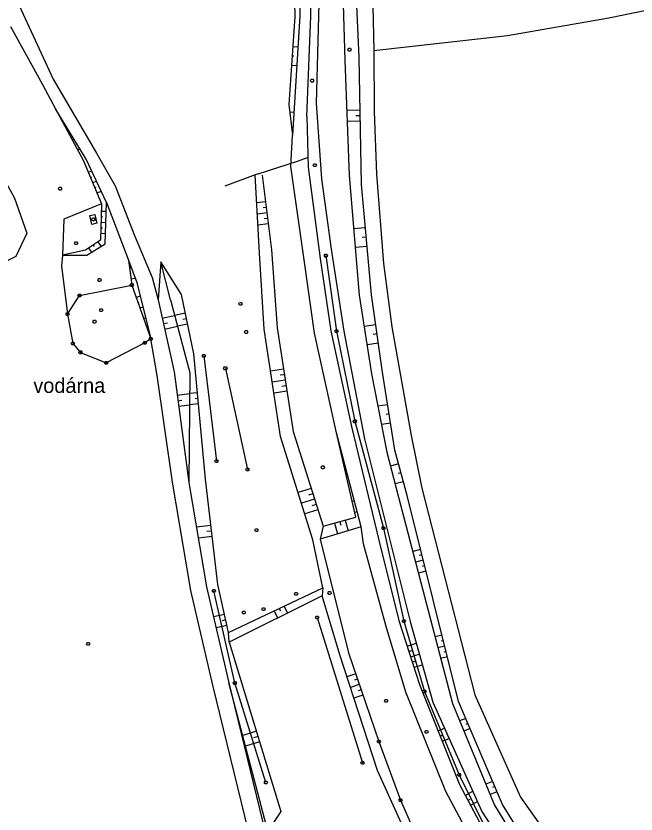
# Model space of a CAD drawing. Extents: x -664960 to -662754, y -993849 to -991145.
# Drawn here: x -663555.7 to -663422.3, y -993033.1 to -992861.4 of the extents above; entities that cross this region are included whole.
import ezdxf

# ---------------------------------------------------------------- set-up
doc = ezdxf.new("R2010")
doc.units = 0
for name, color, linetype in [('Vrstva 13', 7, 'Continuous'), ('Vrstva 24', 7, 'Continuous'), ('Vrstva 27', 7, 'Continuous'), ('Vrstva 29', 7, 'Continuous'), ('Vrstva 33', 7, 'Continuous'), ('Vrstva 63', 7, 'Continuous')]:
    doc.layers.add(name, color=color, linetype=linetype)

msp = doc.modelspace()

# ---------------------------------------------------------------- linework, layer by layer
at = {"layer": 'Vrstva 13'}
for points in [[(-663542.493, -992909.961), (-663542.313, -992910.261), (-663542.493, -992910.561), (-663542.853, -992910.561), (-663543.033, -992910.261), (-663542.853, -992909.961), (-663542.493, -992909.961)], [(-663537.472, -992917.871), (-663537.292, -992918.171), (-663537.472, -992918.471), (-663537.832, -992918.471), (-663538.012, -992918.171), (-663537.832, -992917.871), (-663537.472, -992917.871)], [(-663489.494, -992958.202), (-663489.314, -992958.502), (-663489.494, -992958.802), (-663489.854, -992958.802), (-663490.034, -992958.502), (-663489.854, -992958.202), (-663489.494, -992958.202)], [(-663503.758, -992971.707), (-663503.578, -992972.007), (-663503.758, -992972.307), (-663504.118, -992972.307), (-663504.298, -992972.007), (-663504.118, -992971.707), (-663503.758, -992971.707)], [(-663539.928, -992996.16), (-663539.748, -992996.46), (-663539.928, -992996.76), (-663540.288, -992996.76), (-663540.468, -992996.46), (-663540.288, -992996.16), (-663539.928, -992996.16)], [(-663475.846, -993008.426), (-663475.666, -993008.726), (-663475.846, -993009.026), (-663476.206, -993009.026), (-663476.386, -993008.726), (-663476.206, -993008.426), (-663475.846, -993008.426)], [(-663467.154, -993015.117), (-663466.974, -993015.417), (-663467.154, -993015.717), (-663467.514, -993015.717), (-663467.694, -993015.417), (-663467.514, -993015.117), (-663467.154, -993015.117)]]:
    msp.add_lwpolyline(points, dxfattribs=at)
at = {"layer": 'Vrstva 24'}
msp.add_lwpolyline([(-663503.56, -992895.37), (-663495.1, -992892.65), (-663492.76, -992891.78)], dxfattribs=at)
at = {"layer": 'Vrstva 27'}
for p, q in [((-663493.095, -992883.033), (-663492.82, -992893.94)), ((-663496.5, -992893.77), (-663496.188, -992887.015)), ((-663492.82, -992893.94), (-663490.26, -992913.59)), ((-663536.17, -992901.51), (-663531.47, -992913.88))]:
    msp.add_line(p, q, dxfattribs=at)
for points in [[(-663493.3, -992747.16), (-663493.74, -992757.17), (-663493.888, -992762.726), (-663494.182, -992775.159), (-663494.693, -992783.58), (-663494.915, -992797.656), (-663495.32, -992822.604), (-663494.616, -992861.372), (-663496.188, -992887.015)], [(-663488.658, -992771.319), (-663486.041, -992777.124), (-663484.479, -992778.312), (-663480.688, -992780.627), (-663479.797, -992784.051), (-663480.225, -992798.776), (-663480.106, -992812.528), (-663479.191, -992846.153), (-663478.672, -992868.89), (-663478.583, -992881.904), (-663478.082, -992895.396), (-663476.627, -992914.637), (-663474.815, -992928.231), (-663470.676, -992951.637), (-663468.34, -992962.956), (-663456.927, -993007.431), (-663447.138, -993029.424), (-663438.677, -993041.464), (-663430.737, -993050.315), (-663424.65, -993058.054), (-663424.821, -993065.561), (-663424.273, -993071.083), (-663422.364, -993076.277)], [(-663493.095, -992883.033), (-663492.196, -992861.424), (-663492.956, -992822.595), (-663492.609, -992797.023), (-663492.331, -992783.259), (-663491.101, -992775.678), (-663489.833, -992782.642), (-663491.019, -992797.262), (-663489.769, -992835.934), (-663490.477, -992858.663), (-663491.12, -992880.1), (-663489.906, -992896.409), (-663487.878, -992911.561), (-663485.118, -992929.166), (-663480.702, -992952.347), (-663470.868, -992991.635), (-663466.023, -993009.002), (-663455.437, -993032.516), (-663446.928, -993045.767), (-663436.64, -993058.03)], [(-663442.777, -993044.277), (-663451.02, -993031.047), (-663460.443, -993008.901), (-663471.546, -992964.515), (-663474.13, -992954.774), (-663476.786, -992938.014), (-663479.196, -992921.39), (-663481.361, -992897.65), (-663481.87, -992870.307), (-663482.894, -992846.181), (-663483.445, -992812.781), (-663483.355, -992807.645), (-663486.558, -992815.716), (-663484.937, -992870.853), (-663484.019, -992895.682), (-663481.827, -992921.432), (-663479.164, -992938.361), (-663475.866, -992955.23), (-663473.364, -992964.906), (-663461.79, -993009.293), (-663452.727, -993031.168), (-663444.935, -993044.005)], [(-663555.42, -992858.21), (-663547.62, -992874.94), (-663538.34, -992890.87), (-663534.33, -992897.95), (-663530.16, -992908.58), (-663526.35, -992917.64), (-663525.07, -992922.44)], [(-663556.8, -992863.63), (-663549.94, -992876.15), (-663547.12, -992881.32)], [(-663292.32, -993232.82), (-663314.09, -993212.62), (-663328.7, -993196.3), (-663343.76, -993179.73), (-663358.38, -993164.43), (-663372, -993149.25), (-663389.69, -993127.17), (-663396.18, -993117.78), (-663410.43, -993097.33), (-663424.37, -993080.01), (-663430.1, -993071.8), (-663439.74, -993061.19), (-663449.23, -993051.04), (-663457.96, -993038.08), (-663463.23, -993028.27), (-663471.77, -993006.86), (-663476.02, -992992.74), (-663480.89, -992974.93), (-663481.39, -992971.3), (-663486.69, -992951.1), (-663491.43, -992929.63), (-663493.61, -992914.38), (-663496.5, -992893.77)], [(-663531.47, -992913.88), (-663529.62, -992918.73), (-663526.62, -992930.83)], [(-663490.26, -992913.59), (-663487.91, -992929.15), (-663483.47, -992949.71), (-663477.64, -992974.17), (-663473.27, -992991.48), (-663468.86, -993005.23), (-663460.26, -993026.75), (-663454.82, -993037.02), (-663446.62, -993048.94), (-663437.38, -993059.1)], [(-663525.07, -992922.44), (-663521.64, -992937.94), (-663518.46, -992961.72), (-663514.64, -992984.19), (-663509.85, -993004.83), (-663501.96, -993037.29), (-663497.29, -993056.07), (-663495.2, -993076.09), (-663494.44, -993088.61), (-663492.24, -993113.44), (-663491.4, -993120.78), (-663490.02, -993129.31), (-663486.29, -993143.39), (-663482, -993155.26), (-663474.22, -993166.96), (-663462.98, -993181.7), (-663450.36, -993195.84), (-663435.28, -993211.34), (-663418, -993227.21), (-663404.31, -993240.04), (-663391.6, -993253.92), (-663379.85, -993267.71)], [(-663381.88, -993269.82), (-663387.32, -993265.33), (-663393.79, -993257), (-663407.95, -993241.48), (-663421.02, -993229.28), (-663438.16, -993213.52), (-663452.44, -993198.54), (-663465.76, -993183.63), (-663477.14, -993169.29), (-663485.35, -993156.12), (-663489.97, -993144.37), (-663493.8, -993129.17), (-663494.9, -993123.17), (-663495.36, -993113.85), (-663496.9, -993088.93), (-663497.54, -993077.21), (-663500.56, -993056.55), (-663504.87, -993038.7), (-663505.62, -993036.77), (-663513.31, -993005.37), (-663518.03, -992984.98), (-663521.99, -992961.69), (-663525.31, -992938.73), (-663526.62, -992930.83)]]:
    msp.add_lwpolyline(points, dxfattribs=at)
at = {"layer": 'Vrstva 29'}
for points in [[(-663539.74, -992904.28), (-663538.7, -992904.06), (-663538.26, -992905.96), (-663539.31, -992906.21), (-663539.74, -992904.28)], [(-663538.821, -992904.819), (-663538.641, -992905.119), (-663538.821, -992905.419), (-663539.181, -992905.419), (-663539.361, -992905.119), (-663539.181, -992904.819), (-663538.821, -992904.819)]]:
    msp.add_lwpolyline(points, dxfattribs=at)
at = {"layer": 'Vrstva 33'}
for points in [[(-663537.14, -992924.39), (-663536.96, -992924.69), (-663537.14, -992924.99), (-663537.5, -992924.99), (-663537.68, -992924.69), (-663537.5, -992924.39), (-663537.14, -992924.39)], [(-663538.55, -992926.86), (-663538.37, -992927.16), (-663538.55, -992927.46), (-663538.91, -992927.46), (-663539.09, -992927.16), (-663538.91, -992926.86), (-663538.55, -992926.86)]]:
    msp.add_lwpolyline(points, dxfattribs=at)
at = {"layer": 'Vrstva 63'}
for p, q in [((-663496.111, -992867.961), (-663495.025, -992868.038)), ((-663496.253, -992869.956), (-663495.885, -992869.982)), ((-663496.394, -992871.951), (-663495.269, -992872.031)), ((-663481.659, -992881.629), (-663484.537, -992881.682)), ((-663496.785, -992882.1), (-663495.88, -992881.99)), ((-663481.637, -992882.828), (-663482.588, -992882.846)), ((-663545.786, -992883.802), (-663545.663, -992883.735)), ((-663545.218, -992884.859), (-663545.159, -992884.827)), ((-663496.544, -992884.085), (-663496.364, -992884.063)), ((-663481.615, -992884.028), (-663484.448, -992884.081)), ((-663544.65, -992885.916), (-663544.421, -992885.793)), ((-663496.303, -992886.071), (-663496.129, -992886.049)), ((-663544.082, -992886.973), (-663543.988, -992886.922)), ((-663543.514, -992888.03), (-663543.18, -992887.85)), ((-663542.945, -992889.087), (-663542.817, -992889.017)), ((-663542.377, -992890.144), (-663541.939, -992889.908)), ((-663540.059, -992895.006), (-663539.369, -992894.717)), ((-663539.596, -992896.113), (-663539.35, -992896.01)), ((-663539.133, -992897.22), (-663538.346, -992896.891)), ((-663538.669, -992898.327), (-663538.391, -992898.211)), ((-663538.206, -992899.434), (-663537.322, -992899.064)), ((-663501.994, -992901.372), (-663503.858, -992901.608)), ((-663537.274, -992903.345), (-663536.227, -992903.382)), ((-663501.692, -992903.753), (-663503.734, -992904.012)), ((-663501.843, -992902.562), (-663502.494, -992902.645)), ((-663537.315, -992904.545), (-663536.965, -992904.557)), ((-663501.541, -992904.943), (-663502.251, -992905.033)), ((-663537.399, -992906.943), (-663537.045, -992906.955)), ((-663537.357, -992905.744), (-663536.3, -992905.78)), ((-663501.39, -992906.133), (-663503.61, -992906.416)), ((-663480.512, -992906.958), (-663483.039, -992907.189)), ((-663537.44, -992908.142), (-663536.373, -992908.179)), ((-663480.33, -992908.95), (-663481.176, -992909.027)), ((-663539.032, -992910.635), (-663538.817, -992910.949)), ((-663538.041, -992909.957), (-663537.361, -992910.951)), ((-663540.022, -992911.313), (-663539.414, -992912.201)), ((-663480.149, -992910.942), (-663482.7, -992911.174)), ((-663522.42, -992922.47), (-663524.52, -992914.27)), ((-663531.243, -992915.559), (-663530.85, -992915.506)), ((-663531.082, -992916.748), (-663530.858, -992916.718)), ((-663530.921, -992917.937), (-663529.971, -992917.809)), ((-663529.796, -992921.918), (-663528.908, -992921.601)), ((-663529.394, -992923.048), (-663529.135, -992922.956)), ((-663528.991, -992924.178), (-663528.328, -992923.942)), ((-663528.588, -992925.309), (-663528.405, -992925.243)), ((-663528.185, -992926.439), (-663527.747, -992926.283)), ((-663524.195, -992926.392), (-663521.54, -992925.805)), ((-663519.218, -992925.328), (-663521.54, -992925.805)), ((-663523.936, -992927.564), (-663523.036, -992927.365)), ((-663518.735, -992927.679), (-663520.926, -992928.129)), ((-663518.976, -992926.504), (-663519.728, -992926.658)), ((-663478.266, -992927.807), (-663480.767, -992928.17)), ((-663523.677, -992928.736), (-663520.926, -992928.127)), ((-663477.979, -992929.786), (-663478.804, -992929.906)), ((-663477.692, -992931.766), (-663480.146, -992932.121)), ((-663515.24, -992934.51), (-663512.53, -992957.14)), ((-663510.62, -992937.2), (-663505.88, -992958.97)), ((-663498.101, -992937.366), (-663500.878, -992937.792)), ((-663497.737, -992939.738), (-663500.514, -992940.164)), ((-663497.919, -992938.552), (-663498.844, -992938.694)), ((-663497.555, -992940.924), (-663498.48, -992941.066)), ((-663520.966, -992942.98), (-663518.314, -992942.625)), ((-663516.638, -992942.469), (-663518.314, -992942.625)), ((-663497.374, -992942.11), (-663500.15, -992942.536)), ((-663520.807, -992944.169), (-663519.98, -992944.059)), ((-663520.648, -992945.359), (-663518.333, -992945.049)), ((-663516.416, -992944.859), (-663518.333, -992945.038)), ((-663516.527, -992943.664), (-663517.125, -992943.72)), ((-663475.676, -992945.017), (-663477.797, -992945.353)), ((-663475.363, -992946.992), (-663476.046, -992947.101)), ((-663475.05, -992948.968), (-663477.029, -992949.281)), ((-663482.58, -992969.24), (-663486.69, -992951.1)), ((-663473.344, -992957.738), (-663475.097, -992958.203)), ((-663472.831, -992959.671), (-663473.419, -992959.827)), ((-663472.318, -992961.604), (-663474.096, -992962.075)), ((-663492.161, -992963.023), (-663494.952, -992963.91)), ((-663491.435, -992965.311), (-663494.236, -992966.201)), ((-663491.798, -992964.167), (-663492.729, -992964.463)), ((-663483.36, -992965.799), (-663482.863, -992965.686)), ((-663491.071, -992966.455), (-663492.006, -992966.751)), ((-663483.095, -992966.969), (-663482.916, -992966.929)), ((-663490.708, -992967.598), (-663493.52, -992968.491)), ((-663482.829, -992968.139), (-663482.254, -992968.009)), ((-663489.58, -992971.15), (-663482.58, -992969.24)), ((-663487.142, -992970.485), (-663486.507, -992972.815)), ((-663485.985, -992970.169), (-663485.775, -992970.937)), ((-663484.827, -992969.853), (-663484.205, -992972.133)), ((-663513.716, -992970.999), (-663516.82, -992971.369)), ((-663513.573, -992972.19), (-663514.587, -992972.311)), ((-663481.39, -992971.3), (-663490.24, -992973.92)), ((-663513.431, -992973.382), (-663516.417, -992973.738)), ((-663468.631, -992976.169), (-663470.317, -992976.591)), ((-663468.34, -992977.333), (-663468.897, -992977.473)), ((-663468.048, -992978.498), (-663469.711, -992978.914)), ((-663467.466, -992980.826), (-663469.106, -992981.236)), ((-663467.757, -992979.662), (-663468.307, -992979.799)), ((-663500.108, -992989.368), (-663499.384, -992990.903)), ((-663499.023, -992988.856), (-663498.786, -992989.36)), ((-663497.938, -992988.345), (-663497.236, -992989.832)), ((-663510.79, -992990.158), (-663513.136, -992990.67)), ((-663510.534, -992991.331), (-663511.31, -992991.5)), ((-663490.85, -992990.79), (-663481.13, -993022.05)), ((-663510.278, -992992.503), (-663512.594, -992993.008)), ((-663464.016, -992994.616), (-663465.519, -992994.992)), ((-663471.51, -992996.968), (-663469.555, -992996.341)), ((-663463.725, -992995.78), (-663464.222, -992995.905)), ((-663471.143, -992998.111), (-663470.507, -992997.907)), ((-663463.434, -992996.945), (-663464.913, -992997.315)), ((-663463.143, -992998.109), (-663463.631, -992998.231)), ((-663470.777, -992999.253), (-663468.91, -992998.655)), ((-663462.851, -992999.273), (-663464.308, -992999.637)), ((-663470.41, -993000.396), (-663469.803, -993000.201)), ((-663470.044, -993001.539), (-663468.265, -993000.968)), ((-663482.581, -993002.93), (-663484.484, -993003.576)), ((-663481.81, -993005.203), (-663483.736, -993005.856)), ((-663482.195, -993004.067), (-663482.833, -993004.283)), ((-663481.424, -993006.339), (-663482.07, -993006.558)), ((-663481.039, -993007.476), (-663482.989, -993008.137)), ((-663458.914, -993012.494), (-663460.232, -993013.055)), ((-663458.444, -993013.598), (-663458.887, -993013.786)), ((-663503.941, -993015.26), (-663506.877, -993016.155)), ((-663464.878, -993015.194), (-663463.486, -993014.638)), ((-663457.975, -993014.702), (-663459.313, -993015.272)), ((-663503.591, -993016.407), (-663504.584, -993016.71)), ((-663464.433, -993016.309), (-663463.953, -993016.117)), ((-663463.987, -993017.423), (-663462.5, -993016.828)), ((-663503.241, -993017.555), (-663506.267, -993018.478)), ((-663453.136, -993026.074), (-663454.582, -993026.69)), ((-663452.666, -993027.178), (-663453.151, -993027.385)), ((-663459.03, -993029.073), (-663457.38, -993028.199)), ((-663452.196, -993028.283), (-663453.664, -993028.907)), ((-663458.468, -993030.133), (-663457.941, -993029.854)), ((-663457.906, -993031.194), (-663456.393, -993030.392))]:
    msp.add_line(p, q, dxfattribs=at)
for points in [[(-663493.888, -992762.726), (-663496.142, -992777.214), (-663496.083, -992797.466), (-663496.579, -992822.93), (-663495.652, -992861.485), (-663496.993, -992880.388), (-663496.188, -992887.015)], [(-663363.985, -992907.073), (-663374.41, -992891.386), (-663393.094, -992854.627), (-663428.131, -992861.855), (-663449.923, -992865.664), (-663478.672, -992868.89)], [(-663483.722, -992868.335), (-663483.542, -992868.635), (-663483.722, -992868.935), (-663484.082, -992868.935), (-663484.262, -992868.635), (-663484.082, -992868.335), (-663483.722, -992868.335)], [(-663491.785, -992874.984), (-663491.605, -992875.284), (-663491.785, -992875.584), (-663492.145, -992875.584), (-663492.325, -992875.284), (-663492.145, -992874.984), (-663491.785, -992874.984)], [(-663547.12, -992881.32), (-663541.1, -992892.52), (-663537.22, -992901.79), (-663537.49, -992909.58), (-663540.66, -992911.75), (-663545.65, -992912.85), (-663540.43, -992912.82), (-663536.44, -992910.39), (-663536.17, -992901.51)], [(-663536.17, -992901.51), (-663540.55, -992892.21), (-663547.12, -992881.32)], [(-663491.2, -992893.17), (-663491.02, -992893.47), (-663491.2, -992893.77), (-663491.56, -992893.77), (-663491.74, -992893.47), (-663491.56, -992893.17), (-663491.2, -992893.17)], [(-663503.56, -992895.37), (-663504.17, -992895.57), (-663510.76, -992897.96)], [(-663558.76, -992895.41), (-663555.95, -992900.61), (-663553.28, -992908.14), (-663555.71, -992913.11), (-663558.56, -992914.53), (-663569.41, -992917.2), (-663577.02, -992922.39), (-663583.53, -992932.72)], [(-663489.68, -992984.45), (-663491.78, -992974.06), (-663498.72, -992951.85), (-663502.26, -992928.79), (-663503.3, -992912.43), (-663504.17, -992895.57)], [(-663502.72, -992895.66), (-663500.68, -992911.72), (-663499.46, -992928.5), (-663496.04, -992950.81), (-663489.58, -992971.15), (-663490.24, -992973.92), (-663484.12, -992998.39), (-663477.64, -993017.5), (-663472.94, -993030.11), (-663465.51, -993047.01), (-663461.14, -993055.51), (-663454.98, -993064.07), (-663443.01, -993059.86), (-663449.23, -993051.04)], [(-663545.97, -992898.24), (-663545.79, -992898.54), (-663545.97, -992898.84), (-663546.33, -992898.84), (-663546.51, -992898.54), (-663546.33, -992898.24), (-663545.97, -992898.24)], [(-663537.22, -992901.79), (-663545.32, -992905.12), (-663545.65, -992912.85), (-663545.87, -992915.13), (-663544.55, -992925.53), (-663543.42, -992931.83), (-663541.78, -992933.75), (-663536.28, -992936.02)], [(-663531.47, -992913.88), (-663530.74, -992919.27), (-663526.62, -992930.83)], [(-663509.95, -992994.01), (-663512.2, -992983.69), (-663514.91, -992961), (-663517.42, -992934.09), (-663520.04, -992921.32), (-663524.52, -992914.27), (-663525.07, -992922.44)], [(-663488.8, -992912.64), (-663488.62, -992912.94), (-663488.8, -992913.24), (-663489.16, -992913.24), (-663489.34, -992912.94), (-663489.16, -992912.64), (-663488.8, -992912.64)], [(-663488.98, -992912.94), (-663486.69, -992929.18), (-663482.79, -992948.58), (-663476.6, -992971.57), (-663472.24, -992991.59), (-663467.82, -993006.73), (-663460.34, -993024.66), (-663454.22, -993037), (-663446.26, -993048.23), (-663437.77, -993057.47)], [(-663544.55, -992925.53), (-663542.02, -992921.54), (-663530.74, -992919.27)], [(-663530.56, -992918.97), (-663530.38, -992919.27), (-663530.56, -992919.57), (-663530.92, -992919.57), (-663531.1, -992919.27), (-663530.92, -992918.97), (-663530.56, -992918.97)], [(-663541.84, -992921.24), (-663541.66, -992921.54), (-663541.84, -992921.84), (-663542.2, -992921.84), (-663542.38, -992921.54), (-663542.2, -992921.24), (-663541.84, -992921.24)], [(-663522.42, -992922.47), (-663518.28, -992938.15), (-663518.46, -992961.72)], [(-663507.2, -992923.01), (-663507.02, -992923.31), (-663507.2, -992923.61), (-663507.56, -992923.61), (-663507.74, -992923.31), (-663507.56, -992923.01), (-663507.2, -992923.01)], [(-663544.37, -992925.23), (-663544.19, -992925.53), (-663544.37, -992925.83), (-663544.73, -992925.83), (-663544.91, -992925.53), (-663544.73, -992925.23), (-663544.37, -992925.23)], [(-663505.97, -992929.08), (-663505.79, -992929.38), (-663505.97, -992929.68), (-663506.33, -992929.68), (-663506.51, -992929.38), (-663506.33, -992929.08), (-663505.97, -992929.08)], [(-663486.51, -992928.88), (-663486.33, -992929.18), (-663486.51, -992929.48), (-663486.87, -992929.48), (-663487.05, -992929.18), (-663486.87, -992928.88), (-663486.51, -992928.88)], [(-663526.62, -992930.83), (-663527.91, -992931.7), (-663536.28, -992936.02)], [(-663527.73, -992931.4), (-663527.55, -992931.7), (-663527.73, -992932), (-663528.09, -992932), (-663528.27, -992931.7), (-663528.09, -992931.4), (-663527.73, -992931.4)], [(-663526.44, -992930.53), (-663526.26, -992930.83), (-663526.44, -992931.13), (-663526.8, -992931.13), (-663526.98, -992930.83), (-663526.8, -992930.53), (-663526.44, -992930.53)], [(-663543.24, -992931.53), (-663543.06, -992931.83), (-663543.24, -992932.13), (-663543.6, -992932.13), (-663543.78, -992931.83), (-663543.6, -992931.53), (-663543.24, -992931.53)], [(-663541.6, -992933.45), (-663541.42, -992933.75), (-663541.6, -992934.05), (-663541.96, -992934.05), (-663542.14, -992933.75), (-663541.96, -992933.45), (-663541.6, -992933.45)], [(-663515.06, -992934.21), (-663514.88, -992934.51), (-663515.06, -992934.81), (-663515.42, -992934.81), (-663515.6, -992934.51), (-663515.42, -992934.21), (-663515.06, -992934.21)], [(-663536.1, -992935.72), (-663535.92, -992936.02), (-663536.1, -992936.32), (-663536.46, -992936.32), (-663536.64, -992936.02), (-663536.46, -992935.72), (-663536.1, -992935.72)], [(-663510.44, -992936.9), (-663510.26, -992937.2), (-663510.44, -992937.5), (-663510.8, -992937.5), (-663510.98, -992937.2), (-663510.8, -992936.9), (-663510.44, -992936.9)], [(-663482.61, -992948.28), (-663482.43, -992948.58), (-663482.61, -992948.88), (-663482.97, -992948.88), (-663483.15, -992948.58), (-663482.97, -992948.28), (-663482.61, -992948.28)], [(-663512.35, -992956.84), (-663512.17, -992957.14), (-663512.35, -992957.44), (-663512.71, -992957.44), (-663512.89, -992957.14), (-663512.71, -992956.84), (-663512.35, -992956.84)], [(-663505.7, -992958.67), (-663505.52, -992958.97), (-663505.7, -992959.27), (-663506.06, -992959.27), (-663506.24, -992958.97), (-663506.06, -992958.67), (-663505.7, -992958.67)], [(-663476.42, -992971.27), (-663476.24, -992971.57), (-663476.42, -992971.87), (-663476.78, -992971.87), (-663476.96, -992971.57), (-663476.78, -992971.27), (-663476.42, -992971.27)], [(-663509.79, -992996.09), (-663509.95, -992994.01), (-663489.68, -992984.45), (-663489.83, -992986.14)], [(-663512.94, -992984.74), (-663512.76, -992985.04), (-663512.94, -992985.34), (-663513.3, -992985.34), (-663513.48, -992985.04), (-663513.3, -992984.74), (-663512.94, -992984.74)], [(-663501.9, -993026.28), (-663508.6, -993004.89), (-663513.12, -992985.04)], [(-663439.74, -993061.19), (-663447.96, -993066.95), (-663455.1, -993068.27), (-663462.83, -993055.39), (-663468.65, -993044.14), (-663477.89, -993023.69), (-663486.03, -992998.86), (-663489.83, -992986.14), (-663509.79, -992996.09), (-663498.66, -993032.57), (-663501.47, -993036.75), (-663509.85, -993004.83)], [(-663495.2, -992985.4), (-663495.02, -992985.7), (-663495.2, -992986), (-663495.56, -992986), (-663495.74, -992985.7), (-663495.56, -992985.4), (-663495.2, -992985.4)], [(-663488.01, -992985.22), (-663487.83, -992985.52), (-663488.01, -992985.82), (-663488.37, -992985.82), (-663488.55, -992985.52), (-663488.37, -992985.22), (-663488.01, -992985.22)], [(-663506.43, -992989.42), (-663506.25, -992989.72), (-663506.43, -992990.02), (-663506.79, -992990.02), (-663506.97, -992989.72), (-663506.79, -992989.42), (-663506.43, -992989.42)], [(-663502.25, -992988.71), (-663502.07, -992989.01), (-663502.25, -992989.31), (-663502.61, -992989.31), (-663502.79, -992989.01), (-663502.61, -992988.71), (-663502.25, -992988.71)], [(-663490.67, -992990.49), (-663490.49, -992990.79), (-663490.67, -992991.09), (-663491.03, -992991.09), (-663491.21, -992990.79), (-663491.03, -992990.49), (-663490.67, -992990.49)], [(-663472.06, -992991.29), (-663471.88, -992991.59), (-663472.06, -992991.89), (-663472.42, -992991.89), (-663472.6, -992991.59), (-663472.42, -992991.29), (-663472.06, -992991.29)], [(-663508.42, -993004.59), (-663508.24, -993004.89), (-663508.42, -993005.19), (-663508.78, -993005.19), (-663508.96, -993004.89), (-663508.78, -993004.59), (-663508.42, -993004.59)], [(-663467.64, -993006.43), (-663467.46, -993006.73), (-663467.64, -993007.03), (-663468, -993007.03), (-663468.18, -993006.73), (-663468, -993006.43), (-663467.64, -993006.43)], [(-663477.46, -993017.2), (-663477.28, -993017.5), (-663477.46, -993017.8), (-663477.82, -993017.8), (-663478, -993017.5), (-663477.82, -993017.2), (-663477.46, -993017.2)], [(-663477.64, -993017.5), (-663472.94, -993030.11), (-663465.51, -993047.01)], [(-663480.95, -993021.75), (-663480.77, -993022.05), (-663480.95, -993022.35), (-663481.31, -993022.35), (-663481.49, -993022.05), (-663481.31, -993021.75), (-663480.95, -993021.75)], [(-663460.16, -993024.36), (-663459.98, -993024.66), (-663460.16, -993024.96), (-663460.52, -993024.96), (-663460.7, -993024.66), (-663460.52, -993024.36), (-663460.16, -993024.36)], [(-663501.72, -993025.98), (-663501.54, -993026.28), (-663501.72, -993026.58), (-663502.08, -993026.58), (-663502.26, -993026.28), (-663502.08, -993025.98), (-663501.72, -993025.98)], [(-663472.76, -993029.81), (-663472.58, -993030.11), (-663472.76, -993030.41), (-663473.12, -993030.41), (-663473.3, -993030.11), (-663473.12, -993029.81), (-663472.76, -993029.81)]]:
    msp.add_lwpolyline(points, dxfattribs=at)

# ---------------------------------------------------------------- texts
msp.add_text('vodárna', height=3.2, dxfattribs=at).set_placement((-663551.915, -992942.479))

doc.saveas('drawing.dxf')
